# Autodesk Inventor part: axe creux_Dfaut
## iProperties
Created: 2006-03
Part Number: axe creux_Dfaut
Document SubType Name: Modeling
Designer: Flavien MARTY
Author: Flavien MARTY
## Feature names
1. Base1
